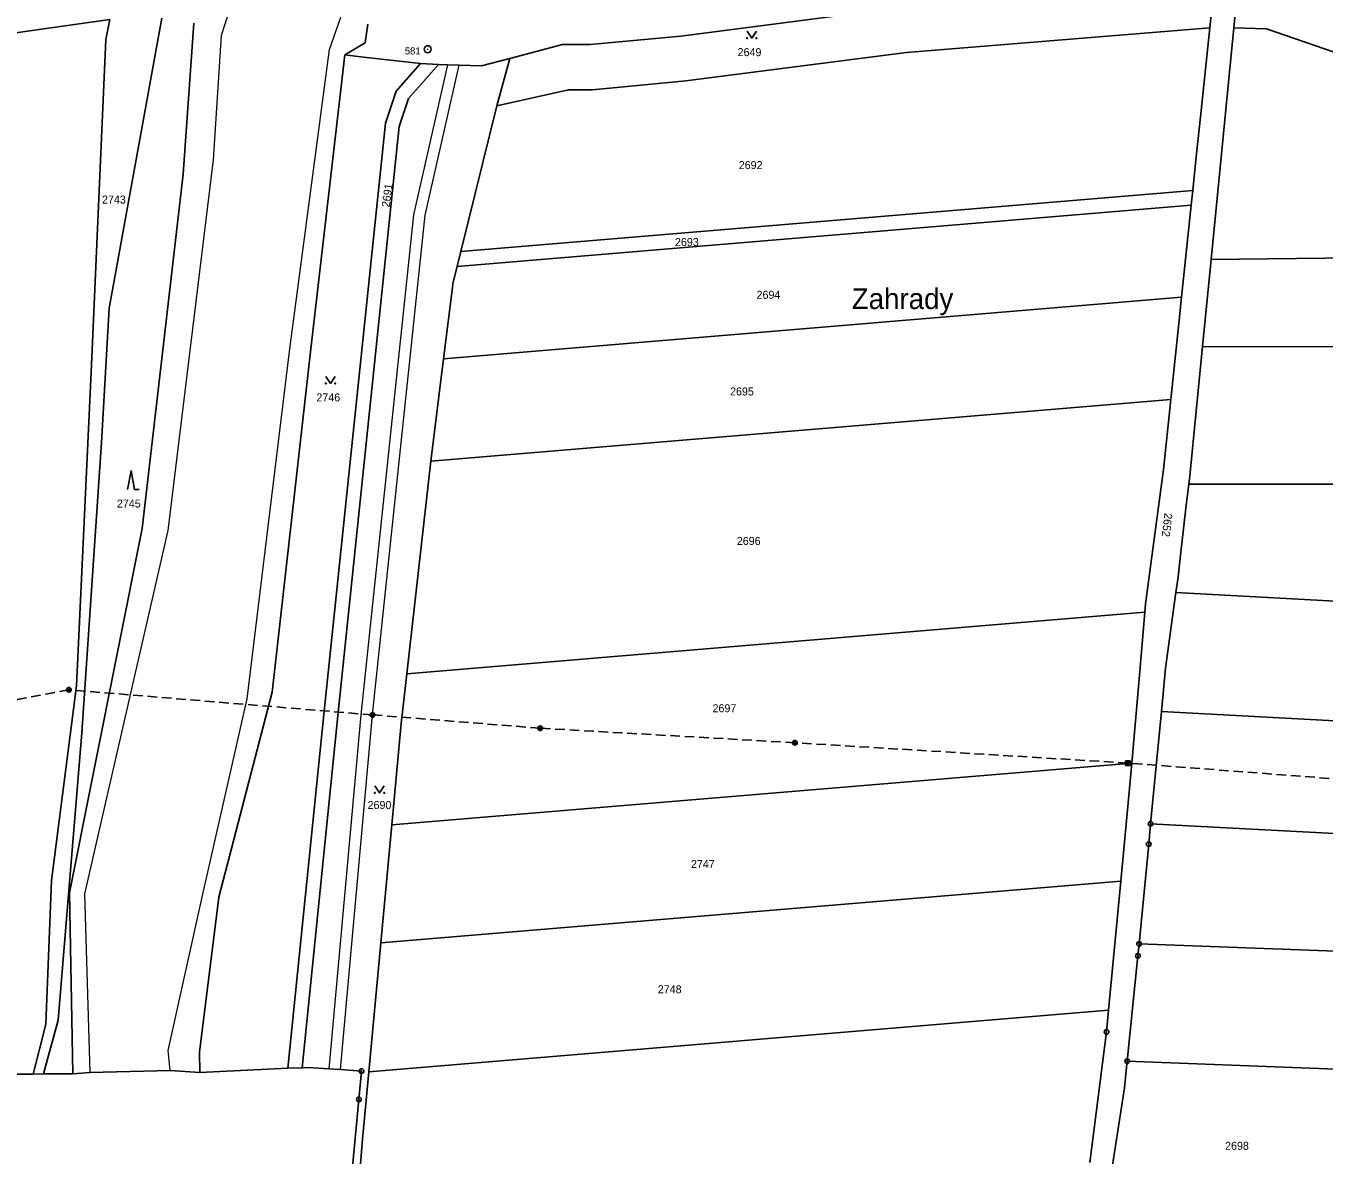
# Model space of a CAD drawing. Extents: x -606517 to -602431, y -1183120 to -1179397.
# Drawn here: x -605998.7 to -605722.9, y -1180939.5 to -1180699.6 of the extents above; entities that cross this region are included whole.
import ezdxf
from ezdxf.enums import TextEntityAlignment as Align

# ---------------------------------------------------------------- set-up
doc = ezdxf.new("R2010")
doc.units = 0
doc.header["$LTSCALE"] = 0.68
doc.linetypes.add('MEDIUM_DASHED', pattern=[4.5, 3, -1.5])
for name, color, linetype, lineweight in [('1', 7, 'Continuous', 25), ('3', 7, 'Continuous', 25), ('4', 7, 'Continuous', 13), ('6', 7, 'Continuous', 25), ('7', 7, 'Continuous', 13), ('8', 7, 'Continuous', 25)]:
    doc.layers.add(name, color=color, linetype=linetype, lineweight=lineweight)
doc.layers.add('2', color=7, linetype='Continuous')

msp = doc.modelspace()

# ---------------------------------------------------------------- linework, layer by layer
at = {"layer": '1'}
for p, q in [((-605812.61, -1180695.69), (-605859.53, -1180701.72)), ((-605747.16, -1180700.01), (-605746.64, -1180695.16)), ((-605741.49, -1180694.16), (-605742.06, -1180699.99)), ((-606043.86, -1180707.12), (-605980.84, -1180698.24)), ((-605980.84, -1180698.24), (-605981.72, -1180702.47)), ((-605981, -1180759.54), (-605969.81, -1180697.93)), ((-605965.3, -1180731.04), (-605963.05, -1180698.98)), ((-605926.03, -1180699.17), (-605926.61, -1180703.2)), ((-605811.6, -1180705.24), (-605747.16, -1180700.01)), ((-605749.13, -1180718.86), (-605747.16, -1180700.01)), ((-605746.89, -1180749.22), (-605742.06, -1180699.99)), ((-605742.06, -1180699.99), (-605735.15, -1180700.18)), ((-605735.15, -1180700.18), (-605710.04, -1180708.85)), ((-605981.72, -1180702.47), (-605984.74, -1180771.57)), ((-605926.61, -1180703.2), (-605930.93, -1180705.72)), ((-605884.7, -1180703.55), (-605895.88, -1180706.46)), ((-605878.81, -1180703.53), (-605884.7, -1180703.55)), ((-605859.53, -1180701.72), (-605878.81, -1180703.53)), ((-605930.93, -1180705.72), (-605938.16, -1180768.22)), ((-605926.96, -1180706.18), (-605930.93, -1180705.72)), ((-605914.86, -1180707.57), (-605926.96, -1180706.18)), ((-605895.88, -1180706.46), (-605901.92, -1180708.03)), ((-605895.88, -1180706.46), (-605898.62, -1180716.56)), ((-605858.47, -1180711.26), (-605811.6, -1180705.24)), ((-605920.04, -1180713.45), (-605914.86, -1180707.57)), ((-605911.03, -1180707.77), (-605917.39, -1180714.98)), ((-605914.86, -1180707.57), (-605911.03, -1180707.77)), ((-605878.34, -1180713.13), (-605858.47, -1180711.26)), ((-605922.33, -1180720.27), (-605920.04, -1180713.45)), ((-605917.39, -1180714.98), (-605919.38, -1180720.91)), ((-605898.62, -1180716.56), (-605883.44, -1180713.15)), ((-605883.44, -1180713.15), (-605878.34, -1180713.13)), ((-605898.62, -1180716.56), (-605906.31, -1180747.52)), ((-605935.31, -1180845.18), (-605922.33, -1180720.27)), ((-605749.96, -1180726.72), (-605749.13, -1180718.86)), ((-605919.38, -1180720.91), (-605932.33, -1180845.49)), ((-605750.24, -1180729.42), (-605749.96, -1180726.72)), ((-605974.01, -1180806.33), (-605965.3, -1180731.04)), ((-605750.78, -1180734.54), (-605750.24, -1180729.42)), ((-605906.31, -1180747.52), (-605750.78, -1180734.54)), ((-605750.78, -1180734.54), (-605751.11, -1180737.68)), ((-605907.1, -1180750.69), (-605751.11, -1180737.68)), ((-605751.11, -1180737.68), (-605753.15, -1180757.2)), ((-605907.1, -1180750.69), (-605906.31, -1180747.52)), ((-605594.1, -1180747.43), (-605746.89, -1180749.22)), ((-605907.93, -1180754.04), (-605907.1, -1180750.69)), ((-605746.89, -1180749.22), (-605748.69, -1180767.72)), ((-605909.96, -1180770.28), (-605907.93, -1180754.04)), ((-605753.15, -1180757.2), (-605909.96, -1180770.28)), ((-605753.15, -1180757.2), (-605753.74, -1180762.81)), ((-605982.64, -1180788.12), (-605981, -1180759.54)), ((-605753.74, -1180762.81), (-605755.43, -1180778.92)), ((-605938.16, -1180768.22), (-605946.35, -1180841.14)), ((-605912.66, -1180792.03), (-605909.96, -1180770.28)), ((-605751.38, -1180795.16), (-605748.69, -1180767.72)), ((-605748.69, -1180767.72), (-605591.11, -1180767.77)), ((-605984.74, -1180771.57), (-605987.95, -1180839.77)), ((-605755.43, -1180778.92), (-605912.66, -1180792.03)), ((-605755.51, -1180779.65), (-605757, -1180793.84)), ((-605755.43, -1180778.92), (-605755.51, -1180779.65)), ((-605986.82, -1180849.76), (-605982.64, -1180788.12)), ((-605917.75, -1180837.23), (-605912.66, -1180792.03)), ((-605757, -1180793.84), (-605760.8, -1180822.38)), ((-605751.61, -1180796.94), (-605751.38, -1180795.16)), ((-605752.18, -1180801.39), (-605751.61, -1180796.94)), ((-605751.61, -1180796.94), (-605586.81, -1180796.99)), ((-605752.75, -1180806.4), (-605752.18, -1180801.39)), ((-605989.42, -1180883.78), (-605974.01, -1180806.33)), ((-605753.32, -1180811.37), (-605752.75, -1180806.4)), ((-605753.92, -1180816.64), (-605753.32, -1180811.37)), ((-605754.37, -1180819.97), (-605753.92, -1180816.64)), ((-605756.56, -1180836.05), (-605754.37, -1180819.97)), ((-605754.37, -1180819.97), (-605573.91, -1180829.6)), ((-605760.8, -1180822.38), (-605760.95, -1180824.14)), ((-605917.75, -1180837.23), (-605760.95, -1180824.14)), ((-605757.45, -1180845.25), (-605756.56, -1180836.05)), ((-605918.94, -1180847.83), (-605917.75, -1180837.23)), ((-605987.95, -1180839.77), (-605993.29, -1180881.18)), ((-605946.35, -1180841.14), (-605957.72, -1180884.72)), ((-605943.03, -1180921.06), (-605935.31, -1180845.18)), ((-605932.33, -1180845.49), (-605940, -1180920.93)), ((-605759.74, -1180869.08), (-605757.45, -1180845.25)), ((-605566.84, -1180855.43), (-605757.45, -1180845.25)), ((-605991.85, -1180910.83), (-605986.82, -1180849.76)), ((-605920.95, -1180869.32), (-605918.94, -1180847.83)), ((-605920.95, -1180869.32), (-605763.75, -1180856.21)), ((-605763.75, -1180856.21), (-605764.48, -1180864.63)), ((-605764.48, -1180864.63), (-605766.06, -1180881.28)), ((-605923.3, -1180894.4), (-605920.95, -1180869.32)), ((-605760.15, -1180873.4), (-605759.74, -1180869.08)), ((-605759.74, -1180869.08), (-605560.54, -1180879.72)), ((-605762.19, -1180894.64), (-605760.15, -1180873.4)), ((-605993.29, -1180881.18), (-605994.49, -1180911.69)), ((-605923.3, -1180894.4), (-605766.06, -1180881.28)), ((-605988.74, -1180922.2), (-605989.42, -1180883.78)), ((-605957.72, -1180884.72), (-605961.83, -1180917.63)), ((-605925.86, -1180921.83), (-605923.3, -1180894.4)), ((-605764.72, -1180919.56), (-605762.44, -1180897.19)), ((-605762.44, -1180897.19), (-605762.19, -1180894.64)), ((-605571.07, -1180901.77), (-605762.19, -1180894.64)), ((-605994.95, -1180922.25), (-605991.85, -1180910.83)), ((-605768.66, -1180908.71), (-605769.1, -1180913.31)), ((-605994.49, -1180911.69), (-605997.16, -1180922.27)), ((-605769.1, -1180913.31), (-605772.66, -1180941.08)), ((-605961.83, -1180917.63), (-605961.74, -1180921.95)), ((-605985.09, -1180921.96), (-605988.74, -1180922.2)), ((-605968.06, -1180921.56), (-605985.09, -1180921.96)), ((-605961.74, -1180921.95), (-605968.06, -1180921.56)), ((-605961.74, -1180921.95), (-605943.03, -1180921.06)), ((-605940, -1180920.93), (-605943.03, -1180921.06)), ((-605940, -1180920.93), (-605938.83, -1180920.87)), ((-605931.86, -1180921.34), (-605927.38, -1180921.64)), ((-605927.38, -1180921.64), (-605927.95, -1180927.66)), ((-605927.2, -1180936.1), (-605925.86, -1180921.83)), ((-605764.92, -1180921.5), (-605765.31, -1180925.23)), ((-605764.72, -1180919.56), (-605764.92, -1180921.5)), ((-605694.69, -1180922.18), (-605764.72, -1180919.56)), ((-605997.16, -1180922.27), (-606064.25, -1180922.88)), ((-605997.16, -1180922.27), (-605994.95, -1180922.25)), ((-605992.61, -1180922.23), (-605994.95, -1180922.25)), ((-605989.74, -1180922.2), (-605992.61, -1180922.23)), ((-605988.74, -1180922.2), (-605989.74, -1180922.2)), ((-605765.31, -1180925.23), (-605769, -1180948.86)), ((-605927.95, -1180927.66), (-605930.47, -1180954.45)), ((-605930.21, -1180973.32), (-605927.2, -1180936.1))]:
    msp.add_line(p, q, dxfattribs=at)
for points in [[(-605901.92, -1180708.03), (-605906.63, -1180707.9), (-605909.14, -1180707.83), (-605911.03, -1180707.77)], [(-605760.95, -1180824.14), (-605762.12, -1180837.52), (-605763.75, -1180856.21)], [(-605766.06, -1180881.28), (-605768.66, -1180908.71), (-605925.86, -1180921.83)], [(-605938.83, -1180920.87), (-605934.35, -1180921.17), (-605931.86, -1180921.34)]]:
    msp.add_lwpolyline(points, dxfattribs=at)
at = {"layer": '3'}
msp.add_line((-605975.62, -1180798.09), (-605974.624, -1180798.09), dxfattribs=at)
for points in [[(-605845.49, -1180700.669), (-605844.49, -1180702.17), (-605843.49, -1180700.669)], [(-605934.98, -1180774.029), (-605933.98, -1180775.53), (-605932.98, -1180774.029)], [(-605975.62, -1180798.09), (-605976.37, -1180794.09), (-605977.12, -1180798.09)], [(-605924.55, -1180861.029), (-605923.55, -1180862.53), (-605922.55, -1180861.029)]]:
    msp.add_lwpolyline(points, dxfattribs=at)
for centre in [(-605845.49, -1180702.1695), (-605843.49, -1180702.1695), (-605934.98, -1180775.5295), (-605932.98, -1180775.5295), (-605924.55, -1180862.5295), (-605922.55, -1180862.5295)]:
    msp.add_circle(centre, 0.1, dxfattribs=at)
at = {"layer": '4'}
for p, q in [((-605913.89, -1180739.76), (-605906.63, -1180707.9)), ((-605927.56, -1180845.94), (-605934.35, -1180921.17)), ((-605968.06, -1180921.56), (-605968.47, -1180917.27))]:
    msp.add_line(p, q, dxfattribs=at)
for points in [[(-605968.47, -1180917.27), (-605961.14, -1180884.08), (-605951.71, -1180842.53), (-605942.64, -1180768.16), (-605934.23, -1180704.59), (-605929.88, -1180692.22), (-605907.45, -1180660.01), (-605887.92, -1180622.48), (-605890.78, -1180584.26), (-605908.04, -1180546.22), (-605921.85, -1180505.79), (-605925.17, -1180482.83), (-605910.96, -1180461.94), (-605887.21, -1180453.14)], [(-605910.05, -1180606.49), (-605910.17, -1180632.08), (-605924.97, -1180653.33), (-605951.33, -1180683.49), (-605957.25, -1180701.62), (-605958.92, -1180728.02), (-605968.58, -1180806.78), (-605986.27, -1180884), (-605985.09, -1180921.96)], [(-605909.14, -1180707.83), (-605916.37, -1180739.74), (-605927.56, -1180845.94)], [(-605931.86, -1180921.34), (-605925.08, -1180845.96), (-605913.89, -1180739.76)]]:
    msp.add_lwpolyline(points, dxfattribs=at)
at = {"layer": '6', "linetype": 'MEDIUM_DASHED'}
msp.add_line((-605764.57, -1180856.2), (-605835.3, -1180851.88), dxfattribs=at)
at = {"layer": '6'}
for p, q in [((-605765.072, -1180855.699), (-605764.071, -1180855.699)), ((-605765.072, -1180856.699), (-605765.072, -1180855.699)), ((-605765.072, -1180855.899), (-605764.071, -1180855.899)), ((-605764.871, -1180856.699), (-605764.871, -1180855.699)), ((-605764.672, -1180856.699), (-605764.672, -1180855.699)), ((-605764.471, -1180856.699), (-605764.471, -1180855.699)), ((-605764.272, -1180856.699), (-605764.272, -1180855.699)), ((-605764.071, -1180856.699), (-605764.071, -1180855.699)), ((-605765.072, -1180856.099), (-605764.071, -1180856.099)), ((-605765.072, -1180856.299), (-605764.071, -1180856.299)), ((-605765.072, -1180856.499), (-605764.071, -1180856.499)), ((-605765.072, -1180856.699), (-605764.071, -1180856.699))]:
    msp.add_line(p, q, dxfattribs=at)
at = {"layer": '6', "linetype": 'MEDIUM_DASHED'}
for points in [[(-605925.08, -1180845.96), (-605989.55, -1180840.64), (-606048.68, -1180851.64), (-606099.74, -1180860.51)], [(-605835.3, -1180851.88), (-605889.43, -1180848.8), (-605925.08, -1180845.96)], [(-605598.29, -1180867.63), (-605651.42, -1180864.34), (-605712.66, -1180860.16), (-605764.57, -1180856.2)]]:
    msp.add_lwpolyline(points, dxfattribs=at)
at = {"layer": '6'}
for centre, radius in [((-605989.5534, -1180840.6399), 0.5), ((-605989.5534, -1180840.6399), 0.4), ((-605989.5534, -1180840.6399), 0.3), ((-605989.5534, -1180840.6399), 0.2), ((-605989.5534, -1180840.6399), 0.1), ((-605925.0834, -1180845.9599), 0.5), ((-605925.0834, -1180845.9599), 0.4), ((-605925.0834, -1180845.9599), 0.3), ((-605925.0834, -1180845.9599), 0.2), ((-605925.0834, -1180845.9599), 0.1), ((-605889.4334, -1180848.7999), 0.5), ((-605889.4334, -1180848.7999), 0.4), ((-605889.4334, -1180848.7999), 0.3), ((-605889.4334, -1180848.7999), 0.2), ((-605889.4334, -1180848.7999), 0.1), ((-605835.3034, -1180851.8799), 0.5), ((-605835.3034, -1180851.8799), 0.4), ((-605835.3034, -1180851.8799), 0.3), ((-605835.3034, -1180851.8799), 0.2), ((-605835.3034, -1180851.8799), 0.1)]:
    msp.add_circle(centre, radius, dxfattribs=at)
at = {"layer": '8'}
for centre, radius in [((-605913.35, -1180704.5198), 0.75), ((-605913.35, -1180704.5198), 0.03), ((-605759.74, -1180869.0799), 0.5), ((-605759.74, -1180869.0799), 0.0303), ((-605760.15, -1180873.3999), 0.5), ((-605760.15, -1180873.3999), 0.0303), ((-605762.19, -1180894.6399), 0.5), ((-605762.44, -1180897.1899), 0.5), ((-605762.44, -1180897.1899), 0.0303), ((-605762.19, -1180894.6399), 0.0303), ((-605769.1, -1180913.3099), 0.5), ((-605769.1, -1180913.3099), 0.0303), ((-605764.72, -1180919.5599), 0.5), ((-605927.38, -1180921.6399), 0.5), ((-605927.38, -1180921.6399), 0.0303), ((-605764.72, -1180919.5599), 0.0303), ((-605927.95, -1180927.6599), 0.5), ((-605927.95, -1180927.6599), 0.0303)]:
    msp.add_circle(centre, radius, dxfattribs=at)

# ---------------------------------------------------------------- texts
at = {"layer": '2'}
for s, p in [('2649', (-605847.49, -1180705.995)), ('2692', (-605847.25, -1180729.995)), ('2743', (-605982.53, -1180737.315)), ('2693', (-605860.8, -1180746.345)), ('2694', (-605843.46, -1180757.545)), ('2746', (-605936.98, -1180779.355)), ('2695', (-605849.1, -1180778.095)), ('2745', (-605979.37, -1180801.915)), ('2696', (-605847.66, -1180809.855)), ('2697', (-605852.82, -1180845.405)), ('2690', (-605926.11, -1180865.965)), ('2747', (-605857.4, -1180878.495)), ('2748', (-605864.45, -1180905.115)), ('2698', (-605743.92, -1180938.375))]:
    msp.add_text(s, height=1.7, dxfattribs=at).set_placement(p)
for s, rotation, p in [('2691', 82, (-605921.449, -1180738.199)), ('2652', 263, (-605756.771, -1180803.018))]:
    msp.add_text(s, height=1.7, rotation=rotation, dxfattribs=at).set_placement(p)
at = {"layer": '7'}
msp.add_text('Zahrady', height=4.4, dxfattribs=at).set_placement((-605812.449, -1180759.73), align=Align.CENTER)
at = {"layer": '8'}
msp.add_text('581', height=1.5, dxfattribs=at).set_placement((-605914.849, -1180705.637), align=Align.RIGHT)

doc.saveas('drawing.dxf')
